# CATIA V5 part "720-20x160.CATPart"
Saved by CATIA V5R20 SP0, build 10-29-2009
Part number: 720-20x160
Definition: NONE
Nomenclature: 720-20x160
Source: Unknown
Description: 720-20x160
Bounding box of the stored display mesh (mm): x 0 to 160, y -10 to 10, z -10 to 10
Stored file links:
  C:\Users\Utente\Desktop\IO LAVORO\3D X SITO CF\X SITO\720\720-20x160.CATPart

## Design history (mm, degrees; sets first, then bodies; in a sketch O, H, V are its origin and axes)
Body1 "720-20x160" (main body)
  Solid1: solid without history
